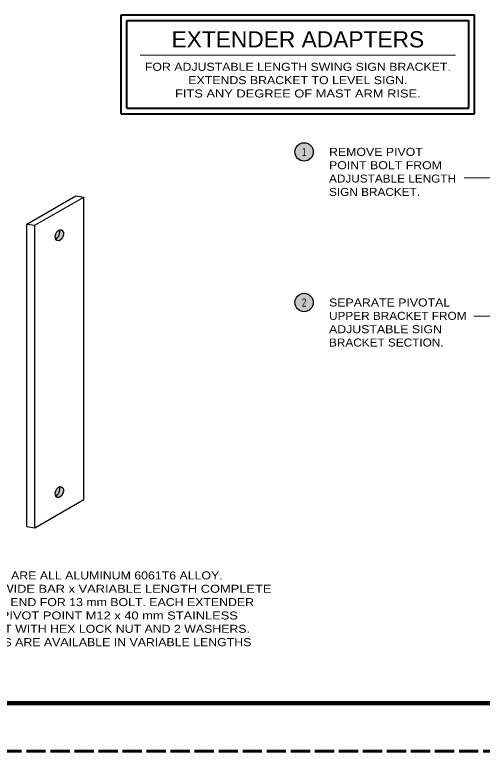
# Model space of a CAD drawing. Extents: x 312583 to 312853, y 144376 to 144586.
# Drawn here: x 312635.1 to 312678.9, y 144418.6 to 144487.6 of the extents above; entities that cross this region are included whole.
import ezdxf
from ezdxf.enums import TextEntityAlignment as Align

# ---------------------------------------------------------------- set-up
doc = ezdxf.new("R2010")
doc.units = 0
doc.header["$LTSCALE"] = 0.3
doc.linetypes.add('LONG_DASHED', pattern=[7.5, 6, -1.5])
for name, color, linetype, lineweight in [('1', 7, 'Continuous', 25), ('2', 7, 'Continuous', 13), ('63', 7, 'LONG_DASHED', 60)]:
    doc.layers.add(name, color=color, linetype=linetype, lineweight=lineweight)

msp = doc.modelspace()

# ---------------------------------------------------------------- hatches: boundary and pattern name
at = {"layer": '1'}
h = msp.add_hatch(color=256, dxfattribs=at)
edge = h.paths.add_edge_path()
edge.add_ellipse((312639.2832, 144466.9059), major_axis=(0.2049, 0.5042), ratio=0.649846, start_angle=0, end_angle=360)
h = msp.add_hatch(color=256, dxfattribs=at)
edge = h.paths.add_edge_path()
edge.add_ellipse((312639.2832, 144442.8528), major_axis=(0.2049, 0.5042), ratio=0.649846, start_angle=0, end_angle=360)
at = {"layer": '2'}
for points in [[(312663.0606, 144474.7131, 1), (312661.3414, 144474.7131, 1)], [(312663.0606, 144460.6093, 1), (312661.3414, 144460.6093, 1)]]:
    msp.add_hatch(color=256, dxfattribs=at).paths.add_polyline_path(points)

# ---------------------------------------------------------------- linework, layer by layer
at = {"layer": '1'}
for p, q in [((312636.9937, 144467.8399), (312641.5727, 144470.4836)), ((312641.5727, 144442.1503), (312641.5727, 144470.4836)), ((312636.2437, 144467.951), (312636.9937, 144467.8399)), ((312636.2437, 144439.6177), (312636.2437, 144467.951)), ((312636.9937, 144439.5066), (312636.9937, 144467.8399)), ((312636.9937, 144439.5066), (312641.5727, 144442.1503)), ((312636.2437, 144439.6177), (312636.9937, 144439.5066))]:
    msp.add_line(p, q, dxfattribs=at)
at = {"layer": '1', "lineweight": 158}
msp.add_line((312616.5, 144423.0846), (312849, 144423.0846), dxfattribs=at)
at = {"layer": '1'}
msp.add_lwpolyline([(312636.2437, 144467.951), (312640.8227, 144470.5947), (312641.5727, 144470.4836)], dxfattribs=at)
for centre in [(312639.2832, 144466.9059), (312639.2832, 144442.8528)]:
    msp.add_ellipse(centre, major_axis=(0.2049, 0.5042), ratio=0.649846, dxfattribs=at)
for centre in [(312638.9366, 144467.0447), (312638.9366, 144442.9916)]:
    msp.add_ellipse(centre, major_axis=(0.2049, 0.5042), ratio=0.649846, start_param=3.701042, end_param=5.7298077, dxfattribs=at)
at = {"layer": '2', "lineweight": 40}
for p, q in [((312645.0729, 144478.2665), (312645.0729, 144487.5573)), ((312645.0729, 144487.5573), (312678.1575, 144487.5573)), ((312678.1575, 144478.2665), (312678.1575, 144487.5573)), ((312645.6118, 144478.8055), (312645.6118, 144487.0183)), ((312645.6118, 144487.0183), (312677.6118, 144487.0183)), ((312677.6118, 144478.8055), (312677.6118, 144487.0183)), ((312645.6118, 144478.8055), (312677.6118, 144478.8055)), ((312645.0729, 144478.2665), (312678.1575, 144478.2665))]:
    msp.add_line(p, q, dxfattribs=at)
at = {"layer": '2'}
for p, q in [((312646.8618, 144483.7624), (312676.3618, 144483.7624)), ((312677.1936, 144472.2869), (312683.7181, 144472.2869))]:
    msp.add_line(p, q, dxfattribs=at)
msp.add_lwpolyline([(312678.0865, 144459.3425), (312679.5982, 144459.3425), (312683.7181, 144461.4126)], dxfattribs=at)
at = {"layer": '2', "lineweight": 25}
for centre in [(312662.201, 144474.7131), (312662.201, 144460.6093)]:
    msp.add_circle(centre, 0.8596, dxfattribs=at)
at = {"layer": '63'}
msp.add_line((312851.75, 144418.5846), (312583.526, 144418.5846), dxfattribs=at)

# ---------------------------------------------------------------- texts
at = {"layer": '2'}
for s, height, width, p in [('EXTENDER ADAPTERS', 1.516, 1.05, (312661.6118, 144484.4977)), ('FOR ADJUSTABLE LENGTH SWING SIGN BRACKET.', 0.75, 1.15, (312661.6118, 144482.3065)), ('EXTENDS BRACKET TO LEVEL SIGN.', 0.75, 1.15, (312661.6118, 144481.0565)), ('FITS ANY DEGREE OF MAST ARM RISE.', 0.75, 1.2, (312661.6118, 144479.8065)), ('1', 0.75, 0.5, (312662.2009, 144474.3381)), ('2', 0.75, 0.75, (312662.2009, 144460.2343))]:
    msp.add_text(s, height=height, dxfattribs=dict(at, width=width)).set_placement(p, align=Align.CENTER)
for s, width, p in [('REMOVE PIVOT ', 1.15, (312664.5308, 144474.3381)), ('POINT BOLT FROM', 1.15, (312664.5308, 144473.0881)), ('ADJUSTABLE LENGTH ', 1.1, (312664.5308, 144471.8381)), ('SIGN BRACKET.', 1.1, (312664.5308, 144470.5881)), ('SEPARATE PIVOTAL ', 1.15, (312664.5308, 144460.2343)), ('UPPER BRACKET FROM', 1.1, (312664.5308, 144458.9843)), ('ADJUSTABLE SIGN ', 1.15, (312664.5308, 144457.7343)), ('BRACKET SECTION.', 1.1, (312664.5308, 144456.4843)), ('EXTENDER ADAPTERS ARE ALL ALUMINUM 6061T6 ALLOY.', 1.15, (312621.6238, 144434.6762)), ('9 mm THICK x 63 mm WIDE BAR x VARIABLE LENGTH COMPLETE', 1.2, (312621.6238, 144433.4262)), ('WITH ONE HOLE EACH END FOR 13 mm BOLT. EACH EXTENDER', 1.15, (312621.6238, 144432.1762)), ('BAR INCLUDES ONE PIVOT POINT M12 x 40 mm STAINLESS', 1.2, (312621.6238, 144430.9262)), ('STEEL HEX HEAD BOLT WITH HEX LOCK NUT AND 2 WASHERS.', 1.15, (312621.6238, 144429.6762)), ('(EXTENDER ADAPTERS ARE AVAILABLE IN VARIABLE LENGTHS', 1.15, (312621.6238, 144428.4262))]:
    msp.add_text(s, height=0.75, dxfattribs=dict(at, width=width)).set_placement(p)

doc.saveas('drawing.dxf')
